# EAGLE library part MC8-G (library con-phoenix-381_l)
Mini-Combicon 3.81mm horizontal 8-polig (mit Gegenstecker)
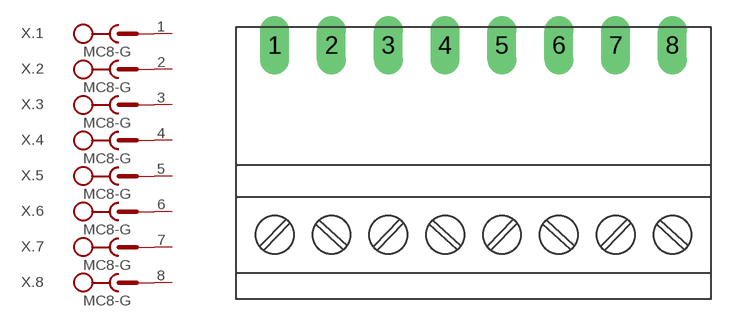
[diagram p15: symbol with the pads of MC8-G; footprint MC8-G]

Designator prefix X; gates .1=SK+V .2=SK+V .3=SK+V .4=SK+V .5=SK+V .6=SK+V .7=SK+V .8=SK+V

## MC8-G  [MC8-G]
1  .1:SK  pas
2  .2:SK  pas
3  .3:SK  pas
4  .4:SK  pas
5  .5:SK  pas
6  .6:SK  pas
7  .7:SK  pas
8  .8:SK  pas

## Footprint MC8-G (pad centres in mm)
Mini-Combicon 3.81mm horizontal 8-polig (mit Gegenstecker)
drill 1.3 long: 1 -13.335,0; 2 -9.525,0; 3 -5.715,0; 4 -1.905,0; 5 1.905,0; 6 5.715,0; 7 9.525,0; 8 13.335,0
